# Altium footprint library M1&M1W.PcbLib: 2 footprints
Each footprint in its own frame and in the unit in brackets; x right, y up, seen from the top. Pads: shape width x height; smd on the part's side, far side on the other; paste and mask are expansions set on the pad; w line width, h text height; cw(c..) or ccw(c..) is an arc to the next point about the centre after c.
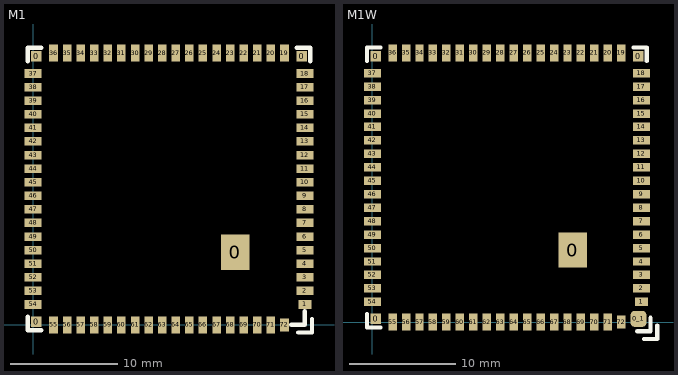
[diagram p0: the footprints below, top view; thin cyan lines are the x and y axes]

## M1 [mm]
height 8.2
pads (76):
  rect 1x1 smd mask+0.051: 0(0.3,0.3) 0(0.3,25.1) 0(25.1,25.1)
  rect 2.667x3.302 smd mask+0.051: 0(18.9,6.8)
  rect 1.2x0.8 smd mask+0.051: 1(25.4,1.905)
  rect 1.6x0.8 smd mask+0.051: 2(25.4,3.175) 3(25.4,4.445) 4(25.4,5.715) 5(25.4,6.985) 6(25.4,8.255) 7(25.4,9.525) 8(25.4,10.795) 9(25.4,12.065) 10(25.4,13.335) 11(25.4,14.605) 12(25.4,15.875) 13(25.4,17.145) 14(25.4,18.415) 15(25.4,19.685) 16(25.4,20.955) 17(25.4,22.225) 18(25.4,23.495) 37(0,23.495) 38(0,22.225) 39(0,20.955) 40(0,19.685) 41(0,18.415) 42(0,17.145) 43(0,15.875) 44(0,14.605) 45(0,13.335) 46(0,12.065) 47(0,10.795) 48(0,9.525) 49(0,8.255) 50(0,6.985) 51(0,5.715) 52(0,4.445) 53(0,3.175) 54(0,1.905)
  rect 0.8x1.6 smd mask+0.051: 19(23.495,25.4) 20(22.225,25.4) 21(20.955,25.4) 22(19.685,25.4) 23(18.415,25.4) 24(17.145,25.4) 25(15.875,25.4) 26(14.605,25.4) 27(13.335,25.4) 28(12.065,25.4) 29(10.795,25.4) 30(9.525,25.4) 31(8.255,25.4) 32(6.985,25.4) 33(5.715,25.4) 34(4.445,25.4) 35(3.175,25.4) 36(1.905,25.4) 55(1.905,0) 56(3.175,0) 57(4.445,0) 58(5.715,0) 59(6.985,0) 60(8.255,0) 61(9.525,0) 62(10.795,0) 63(12.065,0) 64(13.335,0) 65(14.605,0) 66(15.875,0) 67(17.145,0) 68(18.415,0) 69(19.685,0) 70(20.955,0) 71(22.225,0)
  rect 0.8x1.2 smd mask+0.051: 72(23.495,0)
Top Overlay:
  lines w0.4: -0.508,0.762 -0.508,-0.508 0.762,-0.508 ; -0.508,24.638 -0.508,25.908 0.762,25.908 ; 24.13,0 25.4,0 25.4,1.27 ; 24.638,25.908 25.908,25.908 25.908,24.638 ; 24.79,-0.711 26.06,-0.711 26.06,0.559
Top Paste:
  rectangle: 24.387,-0.889 26.284,1.034
  region: 24.6,25.987 24.6,24.6 25.994,24.6 25.994,25.987
  region: 0.8,-0.587 0.8,0.8 -0.594,0.8 -0.594,-0.587
  rectangle: -0.587,24.6 0.8,25.994
  rectangle: 25.941,1.504 26.7,2.304
  rectangle: 25.941,2.774 26.7,3.574
  rectangle: 25.941,5.314 26.7,6.114
  rectangle: 25.941,4.044 26.7,4.844
  rectangle: 25.941,9.124 26.7,9.924
  rectangle: 25.941,10.394 26.7,11.194
  rectangle: 25.941,7.854 26.7,8.654
  rectangle: 25.941,6.584 26.7,7.384
  rectangle: 25.941,16.744 26.7,17.544
  rectangle: 25.941,18.014 26.7,18.814
  rectangle: 25.941,20.554 26.7,21.354
  rectangle: 25.941,19.284 26.7,20.084
  rectangle: 25.941,14.204 26.7,15.004
  rectangle: 25.941,15.474 26.7,16.274
  rectangle: 25.941,12.934 26.7,13.734
  rectangle: 25.941,11.664 26.7,12.464
  rectangle: 25.941,21.824 26.7,22.624
  rectangle: 25.941,23.094 26.7,23.894
  region: 2.306,25.941 2.306,26.7 1.506,26.7 1.506,25.941
  region: 3.576,25.941 3.576,26.7 2.776,26.7 2.776,25.941
  region: 13.736,25.941 13.736,26.7 12.936,26.7 12.936,25.941
  region: 12.466,25.941 12.466,26.7 11.666,26.7 11.666,25.941
  region: 9.926,25.941 9.926,26.7 9.126,26.7 9.126,25.941
  region: 11.196,25.941 11.196,26.7 10.396,26.7 10.396,25.941
  region: 6.116,25.941 6.116,26.7 5.316,26.7 5.316,25.941
  region: 4.846,25.941 4.846,26.7 4.046,26.7 4.046,25.941
  region: 7.386,25.941 7.386,26.7 6.586,26.7 6.586,25.941
  region: 8.656,25.941 8.656,26.7 7.856,26.7 7.856,25.941
  region: 18.816,25.941 18.816,26.7 18.016,26.7 18.016,25.941
  region: 17.546,25.941 17.546,26.7 16.746,26.7 16.746,25.941
  region: 15.006,25.941 15.006,26.7 14.206,26.7 14.206,25.941
  region: 16.276,25.941 16.276,26.7 15.476,26.7 15.476,25.941
  region: 21.356,25.941 21.356,26.7 20.556,26.7 20.556,25.941
  region: 20.086,25.941 20.086,26.7 19.286,26.7 19.286,25.941
  region: 22.626,25.941 22.626,26.7 21.826,26.7 21.826,25.941
  region: 23.896,25.941 23.896,26.7 23.096,26.7 23.096,25.941
  region: -0.541,2.306 -1.3,2.306 -1.3,1.506 -0.541,1.506
  region: -0.541,3.576 -1.3,3.576 -1.3,2.776 -0.541,2.776
  region: -0.541,13.736 -1.3,13.736 -1.3,12.936 -0.541,12.936
  region: -0.541,12.466 -1.3,12.466 -1.3,11.666 -0.541,11.666
  region: -0.541,9.926 -1.3,9.926 -1.3,9.126 -0.541,9.126
  region: -0.541,11.196 -1.3,11.196 -1.3,10.396 -0.541,10.396
  region: -0.541,6.116 -1.3,6.116 -1.3,5.316 -0.541,5.316
  region: -0.541,4.846 -1.3,4.846 -1.3,4.046 -0.541,4.046
  region: -0.541,7.386 -1.3,7.386 -1.3,6.586 -0.541,6.586
  region: -0.541,8.656 -1.3,8.656 -1.3,7.856 -0.541,7.856
  region: -0.541,18.816 -1.3,18.816 -1.3,18.016 -0.541,18.016
  region: -0.541,17.546 -1.3,17.546 -1.3,16.746 -0.541,16.746
  region: -0.541,15.006 -1.3,15.006 -1.3,14.206 -0.541,14.206
  region: -0.541,16.276 -1.3,16.276 -1.3,15.476 -0.541,15.476
  region: -0.541,21.356 -1.3,21.356 -1.3,20.556 -0.541,20.556
  region: -0.541,20.086 -1.3,20.086 -1.3,19.286 -0.541,19.286
  region: -0.541,22.626 -1.3,22.626 -1.3,21.826 -0.541,21.826
  region: -0.541,23.896 -1.3,23.896 -1.3,23.096 -0.541,23.096
  region: 23.094,-0.541 23.094,-1.3 23.894,-1.3 23.894,-0.541
  region: 21.824,-0.541 21.824,-1.3 22.624,-1.3 22.624,-0.541
  region: 11.664,-0.541 11.664,-1.3 12.464,-1.3 12.464,-0.541
  region: 12.934,-0.541 12.934,-1.3 13.734,-1.3 13.734,-0.541
  region: 15.474,-0.541 15.474,-1.3 16.274,-1.3 16.274,-0.541
  region: 14.204,-0.541 14.204,-1.3 15.004,-1.3 15.004,-0.541
  region: 19.284,-0.541 19.284,-1.3 20.084,-1.3 20.084,-0.541
  region: 20.554,-0.541 20.554,-1.3 21.354,-1.3 21.354,-0.541
  region: 18.014,-0.541 18.014,-1.3 18.814,-1.3 18.814,-0.541
  region: 16.744,-0.541 16.744,-1.3 17.544,-1.3 17.544,-0.541
  region: 6.584,-0.541 6.584,-1.3 7.384,-1.3 7.384,-0.541
  region: 7.854,-0.541 7.854,-1.3 8.654,-1.3 8.654,-0.541
  region: 10.394,-0.541 10.394,-1.3 11.194,-1.3 11.194,-0.541
  region: 9.124,-0.541 9.124,-1.3 9.924,-1.3 9.924,-0.541
  region: 4.044,-0.541 4.044,-1.3 4.844,-1.3 4.844,-0.541
  region: 5.314,-0.541 5.314,-1.3 6.114,-1.3 6.114,-0.541
  region: 2.774,-0.541 2.774,-1.3 3.574,-1.3 3.574,-0.541
  region: 1.504,-0.541 1.504,-1.3 2.304,-1.3 2.304,-0.541
3D body "K210 core.step": height 3, standoff 0.2, extent 0,0 25.4,25.4

## M1W [mm]
height 8.2
pads (77):
  rect 1x1 smd mask+0.051: 0(0.3,0.3) 0(0.3,25.1) 0(25.1,25.1)
  rect 2.667x3.302 smd mask+0.051: 0(18.9,6.8)
  rrect50% 1.5x1.5 smd mask+0.051: 0_1(25.123,0.3)
  rect 1.2x0.8 smd mask+0.051: 1(25.4,1.905)
  rect 1.6x0.8 smd mask+0.051: 2(25.4,3.175) 3(25.4,4.445) 4(25.4,5.715) 5(25.4,6.985) 6(25.4,8.255) 7(25.4,9.525) 8(25.4,10.795) 9(25.4,12.065) 10(25.4,13.335) 11(25.4,14.605) 12(25.4,15.875) 13(25.4,17.145) 14(25.4,18.415) 15(25.4,19.685) 16(25.4,20.955) 17(25.4,22.225) 18(25.4,23.495) 37(0,23.495) 38(0,22.225) 39(0,20.955) 40(0,19.685) 41(0,18.415) 42(0,17.145) 43(0,15.875) 44(0,14.605) 45(0,13.335) 46(0,12.065) 47(0,10.795) 48(0,9.525) 49(0,8.255) 50(0,6.985) 51(0,5.715) 52(0,4.445) 53(0,3.175) 54(0,1.905)
  rect 0.8x1.6 smd mask+0.051: 19(23.495,25.4) 20(22.225,25.4) 21(20.955,25.4) 22(19.685,25.4) 23(18.415,25.4) 24(17.145,25.4) 25(15.875,25.4) 26(14.605,25.4) 27(13.335,25.4) 28(12.065,25.4) 29(10.795,25.4) 30(9.525,25.4) 31(8.255,25.4) 32(6.985,25.4) 33(5.715,25.4) 34(4.445,25.4) 35(3.175,25.4) 36(1.905,25.4) 55(1.905,0) 56(3.175,0) 57(4.445,0) 58(5.715,0) 59(6.985,0) 60(8.255,0) 61(9.525,0) 62(10.795,0) 63(12.065,0) 64(13.335,0) 65(14.605,0) 66(15.875,0) 67(17.145,0) 68(18.415,0) 69(19.685,0) 70(20.955,0) 71(22.225,0)
  rect 0.8x1.2 smd mask+0.051: 72(23.495,0)
Top Overlay:
  lines w0.4: -0.508,0.762 -0.508,-0.508 0.762,-0.508 ; -0.508,24.638 -0.508,25.908 0.762,25.908 ; 24.638,25.908 25.908,25.908 25.908,24.638 ; 24.994,-0.864 26.264,-0.864 26.264,0.406 ; 25.629,-1.6 26.899,-1.6 26.899,-0.33
Top Paste:
  region: 1.504,-0.541 1.504,-1.3 2.304,-1.3 2.304,-0.541
  region: 2.774,-0.541 2.774,-1.3 3.574,-1.3 3.574,-0.541
  region: 5.314,-0.541 5.314,-1.3 6.114,-1.3 6.114,-0.541
  region: 4.044,-0.541 4.044,-1.3 4.844,-1.3 4.844,-0.541
  region: 9.124,-0.541 9.124,-1.3 9.924,-1.3 9.924,-0.541
  region: 10.394,-0.541 10.394,-1.3 11.194,-1.3 11.194,-0.541
  region: 7.854,-0.541 7.854,-1.3 8.654,-1.3 8.654,-0.541
  region: 6.584,-0.541 6.584,-1.3 7.384,-1.3 7.384,-0.541
  region: 16.744,-0.541 16.744,-1.3 17.544,-1.3 17.544,-0.541
  region: 18.014,-0.541 18.014,-1.3 18.814,-1.3 18.814,-0.541
  region: 20.554,-0.541 20.554,-1.3 21.354,-1.3 21.354,-0.541
  region: 19.284,-0.541 19.284,-1.3 20.084,-1.3 20.084,-0.541
  region: 14.204,-0.541 14.204,-1.3 15.004,-1.3 15.004,-0.541
  region: 15.474,-0.541 15.474,-1.3 16.274,-1.3 16.274,-0.541
  region: 12.934,-0.541 12.934,-1.3 13.734,-1.3 13.734,-0.541
  region: 11.664,-0.541 11.664,-1.3 12.464,-1.3 12.464,-0.541
  region: 21.824,-0.541 21.824,-1.3 22.624,-1.3 22.624,-0.541
  region: 23.094,-0.541 23.094,-1.3 23.894,-1.3 23.894,-0.541
  region: -0.541,23.896 -1.3,23.896 -1.3,23.096 -0.541,23.096
  region: -0.541,22.626 -1.3,22.626 -1.3,21.826 -0.541,21.826
  region: -0.541,20.086 -1.3,20.086 -1.3,19.286 -0.541,19.286
  region: -0.541,21.356 -1.3,21.356 -1.3,20.556 -0.541,20.556
  region: -0.541,16.276 -1.3,16.276 -1.3,15.476 -0.541,15.476
  region: -0.541,15.006 -1.3,15.006 -1.3,14.206 -0.541,14.206
  region: -0.541,17.546 -1.3,17.546 -1.3,16.746 -0.541,16.746
  region: -0.541,18.816 -1.3,18.816 -1.3,18.016 -0.541,18.016
  region: -0.541,8.656 -1.3,8.656 -1.3,7.856 -0.541,7.856
  region: -0.541,7.386 -1.3,7.386 -1.3,6.586 -0.541,6.586
  region: -0.541,4.846 -1.3,4.846 -1.3,4.046 -0.541,4.046
  region: -0.541,6.116 -1.3,6.116 -1.3,5.316 -0.541,5.316
  region: -0.541,11.196 -1.3,11.196 -1.3,10.396 -0.541,10.396
  region: -0.541,9.926 -1.3,9.926 -1.3,9.126 -0.541,9.126
  region: -0.541,12.466 -1.3,12.466 -1.3,11.666 -0.541,11.666
  region: -0.541,13.736 -1.3,13.736 -1.3,12.936 -0.541,12.936
  region: -0.541,3.576 -1.3,3.576 -1.3,2.776 -0.541,2.776
  region: -0.541,2.306 -1.3,2.306 -1.3,1.506 -0.541,1.506
  region: 23.896,25.941 23.896,26.7 23.096,26.7 23.096,25.941
  region: 22.626,25.941 22.626,26.7 21.826,26.7 21.826,25.941
  region: 20.086,25.941 20.086,26.7 19.286,26.7 19.286,25.941
  region: 21.356,25.941 21.356,26.7 20.556,26.7 20.556,25.941
  region: 16.276,25.941 16.276,26.7 15.476,26.7 15.476,25.941
  region: 15.006,25.941 15.006,26.7 14.206,26.7 14.206,25.941
  region: 17.546,25.941 17.546,26.7 16.746,26.7 16.746,25.941
  region: 18.816,25.941 18.816,26.7 18.016,26.7 18.016,25.941
  region: 8.656,25.941 8.656,26.7 7.856,26.7 7.856,25.941
  region: 7.386,25.941 7.386,26.7 6.586,26.7 6.586,25.941
  region: 4.846,25.941 4.846,26.7 4.046,26.7 4.046,25.941
  region: 6.116,25.941 6.116,26.7 5.316,26.7 5.316,25.941
  region: 11.196,25.941 11.196,26.7 10.396,26.7 10.396,25.941
  region: 9.926,25.941 9.926,26.7 9.126,26.7 9.126,25.941
  region: 12.466,25.941 12.466,26.7 11.666,26.7 11.666,25.941
  region: 13.736,25.941 13.736,26.7 12.936,26.7 12.936,25.941
  region: 3.576,25.941 3.576,26.7 2.776,26.7 2.776,25.941
  region: 2.306,25.941 2.306,26.7 1.506,26.7 1.506,25.941
  rectangle: 25.941,23.094 26.7,23.894
  rectangle: 25.941,21.824 26.7,22.624
  rectangle: 25.941,11.664 26.7,12.464
  rectangle: 25.941,12.934 26.7,13.734
  rectangle: 25.941,15.474 26.7,16.274
  rectangle: 25.941,14.204 26.7,15.004
  rectangle: 25.941,19.284 26.7,20.084
  rectangle: 25.941,20.554 26.7,21.354
  rectangle: 25.941,18.014 26.7,18.814
  rectangle: 25.941,16.744 26.7,17.544
  rectangle: 25.941,6.584 26.7,7.384
  rectangle: 25.941,7.854 26.7,8.654
  rectangle: 25.941,10.394 26.7,11.194
  rectangle: 25.941,9.124 26.7,9.924
  rectangle: 25.941,4.044 26.7,4.844
  rectangle: 25.941,5.314 26.7,6.114
  rectangle: 25.941,2.774 26.7,3.574
  rectangle: 25.941,1.504 26.7,2.304
  rectangle: -0.587,24.6 0.8,25.994
  region: 0.8,-0.587 0.8,0.8 -0.594,0.8 -0.594,-0.587
  region: 24.6,25.987 24.6,24.6 25.994,24.6 25.994,25.987
  rectangle: 24.387,-0.889 26.284,1.034
3D body "K210 core.step": height 3, standoff 0.2, extent 0,0 25.4,25.4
